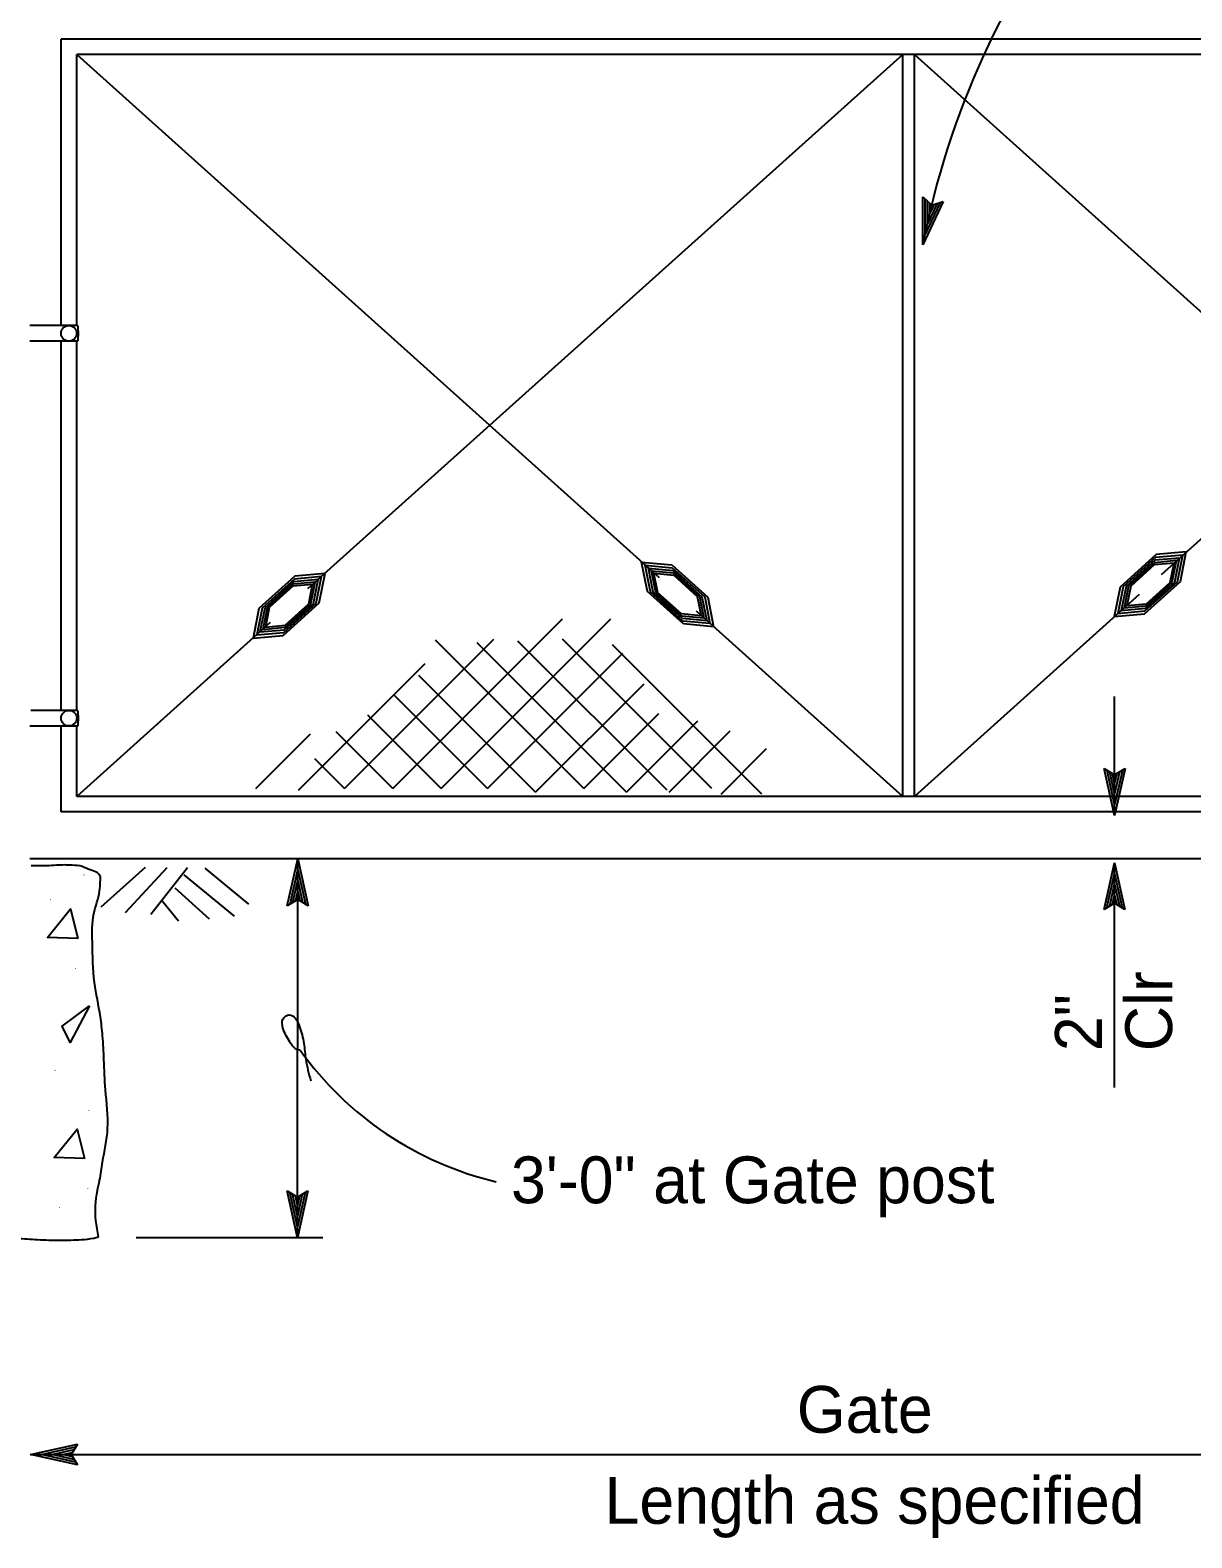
# Model space of a CAD drawing. Extents: x 6710407 to 6714861, y 1868090 to 1871317.
# Drawn here: x 6712595.3 to 6712744.1, y 1870282.8 to 1870475.9 of the extents above; entities that cross this region are included whole.
import ezdxf

# ---------------------------------------------------------------- set-up
doc = ezdxf.new("R2010")
doc.units = 0
for name, color, linetype in [('G-MARK', 7, 'Continuous'), ('G-TEXT', 7, 'Continuous'), ('Nongeo Data(60)', 7, 'Continuous')]:
    doc.layers.add(name, color=color, linetype=linetype)

msp = doc.modelspace()

# ---------------------------------------------------------------- linework, layer by layer
at = {"layer": 'G-MARK'}
for p, q in [((6712734.17, 1870375.31), (6712734.17, 1870390.53)), ((6712629.55, 1870321.23), (6712629.6, 1870369.74)), ((6712734.17, 1870340.48), (6712734.17, 1870369.26)), ((6712608.93, 1870321.25), (6712632.81, 1870321.25)), ((6712595.38, 1870293.46), (6712820.47, 1870293.46))]:
    msp.add_line(p, q, dxfattribs=at)
for centre, radius, start, end in [((6712814.88, 1870427.98), 107.23, 141.731, 169.0219), ((6712664.94, 1870370.31), 43.08, 215.5482, 256.6593)]:
    msp.add_arc(centre, radius, start, end, dxfattribs=at)
msp.add_spline([(6712629.89, 1870345.27), (6712629.56, 1870345.32), (6712628.59, 1870346.3), (6712627.7, 1870348.08), (6712627.7, 1870349.23), (6712628.5, 1870349.77), (6712629.3, 1870349.32), (6712629.83, 1870348.25), (6712630.37, 1870346.12), (6712630.63, 1870344.07), (6712631.26, 1870341.31)], degree=3, dxfattribs=at)
at = {"layer": 'G-TEXT'}
for p, q in [((6712709.62, 1870448.4), (6712709.63, 1870454.55)), ((6712712.24, 1870453.96), (6712709.62, 1870448.4)), ((6712709.63, 1870454.55), (6712709.63, 1870454.55)), ((6712709.63, 1870454.55), (6712710.75, 1870453.48)), ((6712709.92, 1870449.76), (6712709.93, 1870454.24)), ((6712711.84, 1870453.83), (6712709.92, 1870449.75)), ((6712710.22, 1870451.1), (6712710.23, 1870453.99)), ((6712711.44, 1870453.68), (6712710.22, 1870451.1)), ((6712710.53, 1870452.44), (6712710.53, 1870453.68)), ((6712711.06, 1870453.58), (6712710.53, 1870452.44)), ((6712710.75, 1870453.48), (6712712.24, 1870453.96)), ((6712712.24, 1870453.96), (6712712.24, 1870453.96)), ((6712709.62, 1870448.4), (6712709.62, 1870448.4)), ((6712734.17, 1870375.31), (6712732.84, 1870381.31)), ((6712732.84, 1870381.31), (6712732.84, 1870381.31)), ((6712732.84, 1870381.31), (6712734.17, 1870380.51)), ((6712734.17, 1870376.7), (6712733.2, 1870381.07)), ((6712734.17, 1870378.07), (6712733.55, 1870380.9)), ((6712734.17, 1870379.45), (6712733.91, 1870380.66)), ((6712734.17, 1870380.51), (6712735.51, 1870381.31)), ((6712735.51, 1870381.31), (6712734.17, 1870375.31)), ((6712735.16, 1870381.09), (6712734.17, 1870376.69)), ((6712734.8, 1870380.86), (6712734.17, 1870378.07)), ((6712734.45, 1870380.68), (6712734.17, 1870379.45)), ((6712735.51, 1870381.31), (6712735.51, 1870381.31)), ((6712734.17, 1870375.31), (6712734.17, 1870375.31)), ((6712628.26, 1870363.74), (6712629.6, 1870369.74)), ((6712628.61, 1870363.96), (6712629.6, 1870368.36)), ((6712629.6, 1870369.74), (6712629.6, 1870369.74)), ((6712629.6, 1870369.74), (6712630.93, 1870363.74)), ((6712629.61, 1870368.35), (6712630.57, 1870363.97)), ((6712732.83, 1870363.26), (6712734.17, 1870369.26)), ((6712733.19, 1870363.48), (6712734.17, 1870367.88)), ((6712734.17, 1870369.26), (6712734.17, 1870369.26)), ((6712734.17, 1870369.26), (6712735.5, 1870363.26)), ((6712734.17, 1870367.87), (6712735.14, 1870363.5)), ((6712628.97, 1870364.19), (6712629.6, 1870366.98)), ((6712629.6, 1870366.98), (6712630.22, 1870364.15)), ((6712733.55, 1870363.72), (6712734.17, 1870366.5)), ((6712734.17, 1870366.5), (6712734.79, 1870363.68)), ((6712629.6, 1870364.54), (6712628.26, 1870363.74)), ((6712629.32, 1870364.37), (6712629.6, 1870365.59)), ((6712629.6, 1870365.59), (6712629.86, 1870364.38)), ((6712630.93, 1870363.74), (6712629.6, 1870364.54)), ((6712734.17, 1870364.06), (6712732.83, 1870363.26)), ((6712733.89, 1870363.89), (6712734.17, 1870365.12)), ((6712734.17, 1870365.12), (6712734.44, 1870363.91)), ((6712735.5, 1870363.26), (6712734.17, 1870364.06)), ((6712628.26, 1870363.74), (6712628.26, 1870363.74)), ((6712630.93, 1870363.74), (6712630.93, 1870363.74)), ((6712732.83, 1870363.26), (6712732.83, 1870363.26)), ((6712735.5, 1870363.26), (6712735.5, 1870363.26)), ((6712629.55, 1870321.23), (6712628.23, 1870327.23)), ((6712628.23, 1870327.23), (6712628.23, 1870327.23)), ((6712628.23, 1870327.23), (6712629.56, 1870326.43)), ((6712629.55, 1870322.62), (6712628.59, 1870327)), ((6712629.56, 1870323.99), (6712628.94, 1870326.82)), ((6712629.56, 1870325.37), (6712629.3, 1870326.58)), ((6712630.9, 1870327.23), (6712629.55, 1870321.23)), ((6712629.56, 1870326.43), (6712630.9, 1870327.23)), ((6712630.54, 1870327.01), (6712629.56, 1870322.61)), ((6712630.18, 1870326.78), (6712629.56, 1870323.99)), ((6712629.84, 1870326.6), (6712629.56, 1870325.37)), ((6712630.9, 1870327.23), (6712630.9, 1870327.23)), ((6712629.55, 1870321.23), (6712629.55, 1870321.23)), ((6712595.38, 1870293.46), (6712601.38, 1870294.79)), ((6712601.38, 1870294.79), (6712600.58, 1870293.46)), ((6712601.38, 1870294.79), (6712601.38, 1870294.79)), ((6712601.38, 1870292.12), (6712595.38, 1870293.46)), ((6712595.38, 1870293.46), (6712595.38, 1870293.46)), ((6712601.17, 1870292.47), (6712596.76, 1870293.46)), ((6712596.77, 1870293.46), (6712601.15, 1870294.43)), ((6712598.15, 1870293.46), (6712600.97, 1870294.08)), ((6712600.93, 1870292.83), (6712598.15, 1870293.46)), ((6712599.53, 1870293.45), (6712600.74, 1870293.72)), ((6712600.76, 1870293.18), (6712599.53, 1870293.45)), ((6712600.58, 1870293.46), (6712601.38, 1870292.12)), ((6712601.38, 1870292.12), (6712601.38, 1870292.12))]:
    msp.add_line(p, q, dxfattribs=at)
at = {"layer": 'Nongeo Data(60)'}
for p, q in [((6712816.3, 1870474.76), (6712599.3, 1870474.76)), ((6712599.3, 1870438.04), (6712599.3, 1870474.76)), ((6712814.3, 1870472.76), (6712601.3, 1870472.76)), ((6712601.3, 1870438.06), (6712601.3, 1870472.76)), ((6712601.3, 1870472.76), (6712675.86, 1870405.78)), ((6712707.05, 1870472.76), (6712630.86, 1870404.32)), ((6712707.05, 1870377.76), (6712707.05, 1870472.76)), ((6712708.55, 1870377.76), (6712708.55, 1870472.76)), ((6712708.55, 1870472.76), (6712780.87, 1870407.79)), ((6712814.3, 1870472.76), (6712740.11, 1870406.12)), ((6712599.3, 1870438.06), (6712599.3, 1870441.33)), ((6712601.42, 1870438.06), (6712595.3, 1870438.06)), ((6712601.42, 1870436.06), (6712595.3, 1870436.06)), ((6712599.3, 1870392.04), (6712599.3, 1870436.19)), ((6712599.3, 1870433.41), (6712599.3, 1870436.06)), ((6712601.3, 1870388.76), (6712601.3, 1870436.06)), ((6712739.49, 1870408.72), (6712734.89, 1870404.57)), ((6712742.89, 1870408.66), (6712739.42, 1870408.34)), ((6712743.34, 1870409.07), (6712739.49, 1870408.72)), ((6712742.21, 1870405.25), (6712742.89, 1870408.66)), ((6712742.59, 1870405.28), (6712743.34, 1870409.07)), ((6712674.38, 1870403.98), (6712673.62, 1870407.77)), ((6712673.62, 1870407.77), (6712677.47, 1870407.42)), ((6712674.76, 1870403.94), (6712674.08, 1870407.35)), ((6712674.08, 1870407.35), (6712677.54, 1870407.03)), ((6712675.11, 1870403.9), (6712674.49, 1870406.98)), ((6712674.49, 1870406.98), (6712677.61, 1870406.69)), ((6712675.42, 1870403.87), (6712674.87, 1870406.63)), ((6712674.87, 1870406.63), (6712677.67, 1870406.37)), ((6712677.47, 1870407.42), (6712682.08, 1870403.27)), ((6712677.54, 1870407.03), (6712681.69, 1870403.3)), ((6712677.61, 1870406.69), (6712681.34, 1870403.33)), ((6712739.42, 1870408.34), (6712735.28, 1870404.6)), ((6712739.36, 1870407.99), (6712735.63, 1870404.63)), ((6712739.3, 1870407.69), (6712735.94, 1870404.66)), ((6712739.25, 1870407.41), (6712736.23, 1870404.69)), ((6712741.78, 1870407.64), (6712739.25, 1870407.41)), ((6712742.11, 1870407.95), (6712739.3, 1870407.69)), ((6712742.48, 1870408.28), (6712739.36, 1870407.99)), ((6712741.28, 1870405.16), (6712741.78, 1870407.64)), ((6712741.56, 1870405.18), (6712742.11, 1870407.95)), ((6712741.86, 1870405.21), (6712742.48, 1870408.28)), ((6712629.24, 1870405.96), (6712624.63, 1870401.82)), ((6712629.16, 1870405.58), (6712625.02, 1870401.85)), ((6712629.1, 1870405.24), (6712625.36, 1870401.88)), ((6712629.03, 1870404.93), (6712625.67, 1870401.91)), ((6712628.98, 1870404.66), (6712625.95, 1870401.93)), ((6712631.5, 1870404.89), (6712628.98, 1870404.66)), ((6712631.84, 1870405.19), (6712629.03, 1870404.93)), ((6712632.21, 1870405.53), (6712629.1, 1870405.24)), ((6712632.63, 1870405.9), (6712629.16, 1870405.58)), ((6712633.09, 1870406.32), (6712629.24, 1870405.96)), ((6712631.01, 1870402.4), (6712631.5, 1870404.89)), ((6712631.29, 1870402.43), (6712631.84, 1870405.19)), ((6712631.6, 1870402.46), (6712632.21, 1870405.53)), ((6712631.95, 1870402.49), (6712632.63, 1870405.9)), ((6712632.33, 1870402.53), (6712633.09, 1870406.32)), ((6712675.7, 1870403.84), (6712675.2, 1870406.33)), ((6712675.2, 1870406.33), (6712677.73, 1870406.09)), ((6712677.67, 1870406.37), (6712681.03, 1870403.35)), ((6712677.73, 1870406.09), (6712680.75, 1870403.37)), ((6712734.89, 1870404.57), (6712734.13, 1870400.78)), ((6712735.28, 1870404.6), (6712734.6, 1870401.19)), ((6712735.63, 1870404.63), (6712735.01, 1870401.56)), ((6712735.94, 1870404.66), (6712735.39, 1870401.9)), ((6712736.23, 1870404.69), (6712735.73, 1870402.2)), ((6712737.98, 1870401.13), (6712742.59, 1870405.28)), ((6712738.06, 1870401.51), (6712742.21, 1870405.25)), ((6712738.13, 1870401.85), (6712741.86, 1870405.21)), ((6712738.2, 1870402.16), (6712741.56, 1870405.18)), ((6712738.26, 1870402.43), (6712741.28, 1870405.16)), ((6712678.98, 1870399.84), (6712674.38, 1870403.98)), ((6712678.91, 1870400.21), (6712674.76, 1870403.94)), ((6712678.84, 1870400.54), (6712675.11, 1870403.9)), ((6712678.77, 1870400.85), (6712675.42, 1870403.87)), ((6712678.72, 1870401.12), (6712675.7, 1870403.84)), ((6712680.75, 1870403.37), (6712681.24, 1870400.89)), ((6712681.03, 1870403.35), (6712681.58, 1870400.59)), ((6712681.34, 1870403.33), (6712681.96, 1870400.26)), ((6712681.69, 1870403.3), (6712682.37, 1870399.89)), ((6712682.08, 1870403.27), (6712682.83, 1870399.48)), ((6712737.32, 1870403.61), (6712708.55, 1870377.76)), ((6712624.63, 1870401.82), (6712623.88, 1870398.02)), ((6712625.02, 1870401.85), (6712624.34, 1870398.44)), ((6712625.36, 1870401.88), (6712624.75, 1870398.81)), ((6712625.67, 1870401.91), (6712625.12, 1870399.15)), ((6712625.95, 1870401.93), (6712625.46, 1870399.45)), ((6712627.73, 1870398.38), (6712632.33, 1870402.53)), ((6712627.8, 1870398.76), (6712631.95, 1870402.49)), ((6712627.87, 1870399.1), (6712631.6, 1870402.46)), ((6712627.93, 1870399.41), (6712631.29, 1870402.43)), ((6712627.98, 1870399.68), (6712631.01, 1870402.4)), ((6712681.24, 1870400.89), (6712678.72, 1870401.12)), ((6712681.58, 1870400.59), (6712678.77, 1870400.85)), ((6712680.61, 1870401.51), (6712707.05, 1870377.76)), ((6712734.13, 1870400.78), (6712737.98, 1870401.13)), ((6712734.6, 1870401.19), (6712738.06, 1870401.51)), ((6712735.01, 1870401.56), (6712738.13, 1870401.85)), ((6712735.39, 1870401.9), (6712738.2, 1870402.16)), ((6712735.73, 1870402.2), (6712738.26, 1870402.43)), ((6712626.05, 1870400.01), (6712601.3, 1870377.76)), ((6712624.34, 1870398.44), (6712627.8, 1870398.76)), ((6712624.75, 1870398.81), (6712627.87, 1870399.1)), ((6712625.12, 1870399.15), (6712627.93, 1870399.41)), ((6712625.46, 1870399.45), (6712627.98, 1870399.68)), ((6712641.77, 1870378.77), (6712663.49, 1870400.49)), ((6712647.94, 1870378.77), (6712669.66, 1870400.49)), ((6712681.96, 1870400.26), (6712678.84, 1870400.54)), ((6712682.37, 1870399.89), (6712678.91, 1870400.21)), ((6712682.83, 1870399.48), (6712678.98, 1870399.84)), ((6712623.88, 1870398.02), (6712627.73, 1870398.38)), ((6712635.6, 1870378.77), (6712654.71, 1870397.88)), ((6712666.22, 1870378.77), (6712647.23, 1870397.76)), ((6712671.67, 1870378.3), (6712652.57, 1870397.41)), ((6712676.9, 1870378.54), (6712657.79, 1870397.64)), ((6712682.59, 1870378.77), (6712663.49, 1870397.88)), ((6712689, 1870378.06), (6712669.89, 1870397.17)), ((6712653.87, 1870378.77), (6712671.2, 1870396.1)), ((6712629.67, 1870378.54), (6712645.92, 1870394.79)), ((6712660.05, 1870378.3), (6712645.09, 1870393.25)), ((6712599.3, 1870388.76), (6712599.3, 1870392.04)), ((6712599.3, 1870388.82), (6712599.3, 1870392.04)), ((6712660.05, 1870378.3), (6712673.93, 1870392.18)), ((6712653.87, 1870378.77), (6712641.89, 1870390.76)), ((6712601.42, 1870388.76), (6712595.41, 1870388.76)), ((6712647.94, 1870378.77), (6712638.57, 1870388.15)), ((6712666.22, 1870378.77), (6712675.83, 1870388.39)), ((6712671.67, 1870378.3), (6712680.81, 1870387.44)), ((6712601.42, 1870386.76), (6712595.3, 1870386.76)), ((6712599.3, 1870384.12), (6712599.3, 1870386.76)), ((6712601.3, 1870384.12), (6712601.3, 1870386.76)), ((6712601.3, 1870384.12), (6712601.3, 1870386.76)), ((6712624.21, 1870378.77), (6712631.21, 1870385.78)), ((6712641.77, 1870378.77), (6712634.53, 1870386.01)), ((6712677.13, 1870378.3), (6712684.97, 1870386.13)), ((6712599.3, 1870375.76), (6712599.3, 1870384.12)), ((6712601.3, 1870377.76), (6712601.3, 1870384.12)), ((6712683.78, 1870378.06), (6712689.59, 1870383.88)), ((6712635.6, 1870378.77), (6712631.8, 1870382.57)), ((6712814.3, 1870377.76), (6712601.3, 1870377.76)), ((6712816.3, 1870375.76), (6712599.3, 1870375.76)), ((6712820.3, 1870369.76), (6712595.3, 1870369.76)), ((6712610.08, 1870368.64), (6712604.37, 1870363.56)), ((6712612.82, 1870368.6), (6712607.52, 1870362.84)), ((6712615.48, 1870368.6), (6712610.78, 1870362.62)), ((6712617.68, 1870368.58), (6712623.31, 1870363.94)), ((6712613.84, 1870366.05), (6712618.24, 1870362.05)), ((6712615.02, 1870367.7), (6712621.46, 1870362.4)), ((6712612.28, 1870364.34), (6712614.34, 1870361.81))]:
    msp.add_line(p, q, dxfattribs=at)
for points in [[(6712601.45, 1870359.57), (6712597.55, 1870359.68), (6712600.5, 1870363.34)], [(6712602.92, 1870350.91), (6712600.45, 1870346.25), (6712599.42, 1870348.33)], [(6712602.31, 1870331.38), (6712598.41, 1870331.49), (6712601.37, 1870335.15)]]:
    msp.add_lwpolyline(points, close=True, dxfattribs=at)
for centre in [(6712600.29, 1870437.06), (6712600.3, 1870387.77)]:
    msp.add_circle(centre, 1, dxfattribs=at)
for centre in [(6712601.42, 1870437.06), (6712601.42, 1870387.76)]:
    msp.add_ellipse(centre, major_axis=(0, -1), ratio=0.098201, start_param=0, end_param=3.141593, dxfattribs=at)
for points in [[(6712604.32, 1870366.87), (6712604.33, 1870367.47), (6712603.9, 1870367.99), (6712603.04, 1870368.33), (6712602, 1870368.76), (6712600.71, 1870368.94), (6712598.73, 1870368.94), (6712597.44, 1870368.85), (6712596.07, 1870368.85), (6712595.47, 1870368.85)], [(6712604.1, 1870321.34), (6712603.76, 1870323.43), (6712603.95, 1870327.26), (6712604.23, 1870328.57), (6712604.61, 1870330.91), (6712605.26, 1870335.21), (6712604.98, 1870340.17), (6712604.79, 1870344.01), (6712604.61, 1870347.09), (6712604.33, 1870349.53), (6712603.58, 1870353.92), (6712603.3, 1870359.07), (6712603.48, 1870362.72), (6712604.23, 1870365.62), (6712604.32, 1870366.87)], [(6712581.1, 1870321.34), (6712582.71, 1870320.99), (6712584.59, 1870321.27), (6712589.08, 1870321.84), (6712591.23, 1870321.56), (6712593.66, 1870321.18), (6712596.28, 1870320.99), (6712599.18, 1870320.9), (6712601.89, 1870320.99), (6712603.48, 1870321.18), (6712604.1, 1870321.34)]]:
    msp.add_spline(points, degree=3, dxfattribs=at)

# ---------------------------------------------------------------- texts
for s, height, rotation, p in [('.', 0.8, 266.9315, (6712602.2, 1870367.85)), ('.', 0.8, 266.9315, (6712597.91, 1870364.69)), ('.', 0.8, 266.9315, (6712601.07, 1870355.89)), ('Clr', 6, 90, (6712741.54, 1870345.12)), ('2"', 6, 90, (6712732.54, 1870345.12)), ('.', 0.8, 266.9315, (6712598.48, 1870342.83)), ('.', 0.8, 266.9315, (6712602.8, 1870337.65)), ('.', 0.8, 266.9315, (6712602.65, 1870327.67)), ('.', 0.8, 266.9315, (6712599.06, 1870325.28))]:
    msp.add_text(s, height=height, rotation=rotation, dxfattribs=at).set_placement(p)
for s, p in [('3\'-0" at Gate post', (6712656.89, 1870325.64)), ('Gate', (6712693.49, 1870296.24)), ('Length as specified', (6712668.87, 1870284.59))]:
    msp.add_text(s, height=6, dxfattribs=at).set_placement(p)

doc.saveas('drawing.dxf')
